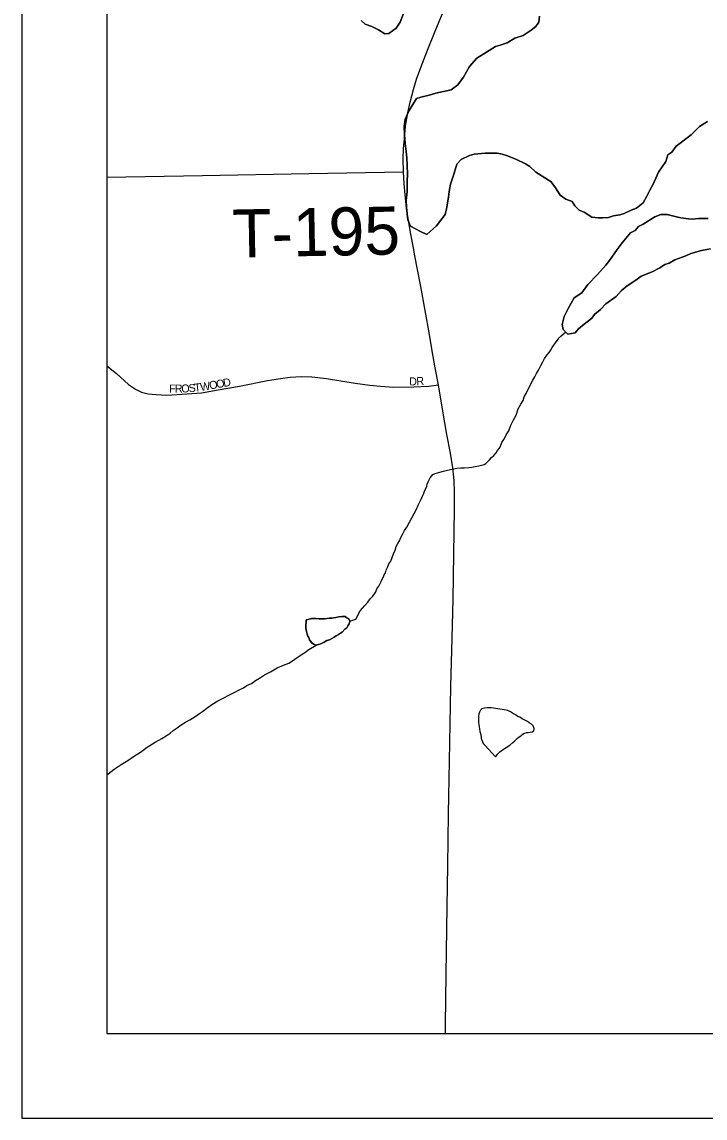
# Model space of a CAD drawing. Extents: x 0 to 34, y 0 to 22.
# Drawn here: x 2.262 to 3.071, y 14.238 to 15.535 of the extents above; entities that cross this region are included whole.
import ezdxf

# ---------------------------------------------------------------- set-up
doc = ezdxf.new("R2010")
doc.units = 0
for name, color, linetype in [('GM_X_County', 7, 'Continuous'), ('GM_X_Major_Lake', 7, 'Continuous'), ('GM_X_Major_River', 7, 'Continuous'), ('GM_X_Minor_Lake', 7, 'Continuous'), ('GM_X_Minor_River', 7, 'Continuous'), ('GM_X_State_Route', 7, 'Continuous'), ('GM_X_Township', 7, 'Continuous'), ('GM_X_Township_Road', 7, 'Continuous'), ('GM_X_Township_Road_Text', 7, 'Continuous'), ('GM_X_Township_Subdivision', 7, 'Continuous'), ('GM_X_Township_Subdivision_Text', 7, 'Continuous'), ('SH_Data', 7, 'Continuous')]:
    doc.layers.add(name, color=color, linetype=linetype)

msp = doc.modelspace()

# ---------------------------------------------------------------- linework, layer by layer
at = {"layer": 'GM_X_County'}
msp.add_lwpolyline([(9.1622, 14.342), (9.1622, 21.1385), (2.3622, 21.1385), (2.3622, 14.3385), (9.0003, 14.3385)], dxfattribs=at)
at = {"layer": 'GM_X_Major_Lake'}
for points in [[(2.6632, 15.5365), (2.6681, 15.5324), (2.6761, 15.5295), (2.6837, 15.5254), (2.6914, 15.5209), (2.6963, 15.5214), (2.7049, 15.5276), (2.7094, 15.5345), (2.7134, 15.5448)], [(2.8745, 15.5419), (2.8738, 15.5347), (2.8701, 15.5293), (2.8648, 15.525), (2.8551, 15.5188), (2.8452, 15.5157), (2.8362, 15.5102), (2.8279, 15.5075), (2.8226, 15.5059), (2.8117, 15.4993), (2.8004, 15.4919), (2.7918, 15.4823), (2.7844, 15.4697), (2.7777, 15.4605), (2.7698, 15.4547), (2.7517, 15.4506), (2.7438, 15.4483), (2.7339, 15.4459), (2.729, 15.4443), (2.7201, 15.4301), (2.7153, 15.4198), (2.7143, 15.4114), (2.7148, 15.4015), (2.7156, 15.3909), (2.7165, 15.3818), (2.7173, 15.3742), (2.7178, 15.3655), (2.7183, 15.3544), (2.718, 15.3468), (2.7178, 15.3343), (2.7168, 15.3236), (2.7169, 15.3153), (2.7186, 15.3009), (2.7217, 15.2933), (2.7335, 15.287), (2.7411, 15.2833), (2.7524, 15.2937), (2.7628, 15.3071), (2.7643, 15.314), (2.7664, 15.3254), (2.7678, 15.3368), (2.7692, 15.3429), (2.7733, 15.3559), (2.7765, 15.3666), (2.7818, 15.372), (2.7916, 15.3767), (2.7972, 15.3786), (2.8101, 15.3796), (2.8245, 15.3797), (2.8302, 15.3783), (2.8355, 15.3768), (2.8466, 15.3724), (2.858, 15.3672), (2.8629, 15.3639), (2.8702, 15.3571), (2.8885, 15.3456), (2.8936, 15.3388), (2.899, 15.3298), (2.9058, 15.3253), (2.9131, 15.3223), (2.9162, 15.3174), (2.9215, 15.3122), (2.9272, 15.31), (2.9364, 15.304), (2.944, 15.303), (2.9493, 15.303)], [(2.9493, 15.303), (2.9561, 15.3035), (2.9621, 15.3055), (2.9697, 15.3067), (2.9746, 15.3083), (2.9829, 15.3122), (2.9893, 15.3146), (2.9972, 15.3211), (3.0016, 15.3288), (3.005, 15.3357), (3.0091, 15.3429), (3.0153, 15.3571), (3.0239, 15.3697), (3.0264, 15.3778), (3.0313, 15.3809), (3.0362, 15.3878), (3.0542, 15.4013), (3.0639, 15.4113), (3.0733, 15.4171)], [(3.0743, 15.3024), (3.0629, 15.3022), (3.0558, 15.3017), (3.0508, 15.3021), (3.0417, 15.3031), (3.0368, 15.3042), (3.0258, 15.3071), (3.0182, 15.3073), (3.011, 15.3042), (2.9971, 15.2957), (2.9915, 15.2929), (2.9877, 15.288), (2.9821, 15.2856), (2.9724, 15.2737), (2.9664, 15.2656), (2.9575, 15.2526), (2.953, 15.2472), (2.9433, 15.2361), (2.9316, 15.2242), (2.9246, 15.2146), (2.9155, 15.2087), (2.9085, 15.1961), (2.9037, 15.1866), (2.9015, 15.177), (2.9027, 15.171), (2.9081, 15.1657), (2.9168, 15.167), (2.9205, 15.1719), (2.9273, 15.1774), (2.9359, 15.1839), (2.94, 15.1893), (2.9468, 15.1947), (2.9531, 15.2016), (2.9652, 15.2101), (2.9715, 15.2171), (2.9783, 15.2228), (2.9884, 15.2294), (2.9948, 15.2341), (3.008, 15.2392), (3.017, 15.2439), (3.0227, 15.2481), (3.028, 15.2497), (3.0347, 15.2536), (3.0479, 15.2583), (3.0536, 15.261), (3.0664, 15.2646), (3.077, 15.2663)]]:
    msp.add_lwpolyline(points, dxfattribs=at)
at = {"layer": 'GM_X_Major_River'}
for points in [[(2.7134, 15.5448), (2.7094, 15.5345), (2.7049, 15.5276), (2.6963, 15.5214), (2.6914, 15.5209), (2.6837, 15.5254), (2.6761, 15.5295), (2.6681, 15.5324), (2.6632, 15.5365)], [(2.9493, 15.303), (2.944, 15.303), (2.9364, 15.304), (2.9272, 15.31), (2.9215, 15.3122), (2.9162, 15.3174), (2.9131, 15.3223), (2.9058, 15.3253), (2.899, 15.3298), (2.8936, 15.3388), (2.8885, 15.3456), (2.8702, 15.3571), (2.8629, 15.3639), (2.858, 15.3672), (2.8466, 15.3724), (2.8355, 15.3768), (2.8302, 15.3783), (2.8245, 15.3797), (2.8101, 15.3796), (2.7972, 15.3786), (2.7916, 15.3767), (2.7818, 15.372), (2.7765, 15.3666), (2.7733, 15.3559), (2.7692, 15.3429), (2.7678, 15.3368), (2.7664, 15.3254), (2.7643, 15.314), (2.7628, 15.3071), (2.7524, 15.2937), (2.7411, 15.2833), (2.7335, 15.287), (2.7217, 15.2933), (2.7186, 15.3009), (2.7169, 15.3153), (2.7168, 15.3236), (2.7178, 15.3343), (2.718, 15.3468), (2.7183, 15.3544), (2.7178, 15.3655), (2.7173, 15.3742), (2.7165, 15.3818), (2.7156, 15.3909), (2.7148, 15.4015), (2.7143, 15.4114), (2.7153, 15.4198), (2.7201, 15.4301), (2.729, 15.4443), (2.7339, 15.4459), (2.7438, 15.4483), (2.7517, 15.4506), (2.7698, 15.4547), (2.7777, 15.4605), (2.7844, 15.4697), (2.7918, 15.4823), (2.8004, 15.4919), (2.8117, 15.4993), (2.8226, 15.5059), (2.8279, 15.5075), (2.8362, 15.5102), (2.8452, 15.5157), (2.8551, 15.5188), (2.8648, 15.525), (2.8701, 15.5293), (2.8738, 15.5347), (2.8745, 15.5419)], [(3.0733, 15.4171), (3.0639, 15.4113), (3.0542, 15.4013), (3.0362, 15.3878), (3.0313, 15.3809), (3.0264, 15.3778), (3.0239, 15.3697), (3.0153, 15.3571), (3.0091, 15.3429), (3.005, 15.3357), (3.0016, 15.3288), (2.9972, 15.3211), (2.9893, 15.3146), (2.9829, 15.3122), (2.9746, 15.3083), (2.9697, 15.3067), (2.9621, 15.3055), (2.9561, 15.3035), (2.9493, 15.303)], [(3.077, 15.2663), (3.0664, 15.2646), (3.0536, 15.261), (3.0479, 15.2583), (3.0347, 15.2536), (3.028, 15.2497), (3.0227, 15.2481), (3.017, 15.2439), (3.008, 15.2392), (2.9948, 15.2341), (2.9884, 15.2294), (2.9783, 15.2228), (2.9715, 15.2171), (2.9652, 15.2101), (2.9531, 15.2016), (2.9468, 15.1947), (2.94, 15.1893), (2.9359, 15.1839), (2.9273, 15.1774), (2.9205, 15.1719), (2.9168, 15.167), (2.9081, 15.1657), (2.9027, 15.171), (2.9015, 15.177), (2.9037, 15.1866), (2.9085, 15.1961), (2.9155, 15.2087), (2.9246, 15.2146), (2.9316, 15.2242), (2.9433, 15.2361), (2.953, 15.2472), (2.9575, 15.2526), (2.9664, 15.2656), (2.9724, 15.2737), (2.9821, 15.2856), (2.9877, 15.288), (2.9915, 15.2929), (2.9971, 15.2957), (3.011, 15.3042), (3.0182, 15.3073), (3.0258, 15.3071), (3.0368, 15.3042), (3.0417, 15.3031), (3.0508, 15.3021), (3.0558, 15.3017), (3.0629, 15.3022), (3.0743, 15.3024)]]:
    msp.add_lwpolyline(points, dxfattribs=at)
at = {"layer": 'GM_X_Minor_Lake'}
for points in [[(2.5984, 14.8276), (2.5992, 14.8278), (2.6019, 14.8286), (2.6049, 14.8291), (2.6099, 14.8292), (2.6137, 14.8289), (2.6171, 14.829), (2.6198, 14.829), (2.6232, 14.8291), (2.6258, 14.8296), (2.6285, 14.8296), (2.6308, 14.8301), (2.6334, 14.8305), (2.6368, 14.831), (2.6403, 14.8314), (2.6425, 14.8315), (2.6444, 14.8315), (2.6464, 14.83), (2.6487, 14.8289), (2.6499, 14.8259), (2.6492, 14.8229), (2.6477, 14.8206), (2.6463, 14.8182), (2.644, 14.8167), (2.6407, 14.8132), (2.6388, 14.812), (2.6366, 14.8104), (2.6339, 14.8088), (2.6313, 14.8072), (2.6287, 14.8057), (2.6257, 14.8041), (2.6226, 14.8032), (2.6196, 14.8013), (2.6178, 14.8005), (2.6155, 14.7993), (2.6129, 14.7984), (2.6102, 14.7976), (2.6068, 14.7987), (2.6048, 14.8005), (2.6021, 14.8039), (2.6013, 14.8066), (2.6001, 14.8084), (2.5993, 14.8107), (2.5988, 14.8137), (2.5984, 14.816), (2.5979, 14.8187), (2.5984, 14.8276)], [(2.5984, 14.8276), (2.5979, 14.8187), (2.5984, 14.816), (2.5988, 14.8137), (2.5993, 14.8107), (2.6001, 14.8084), (2.6013, 14.8066), (2.6021, 14.8039), (2.6048, 14.8005), (2.6068, 14.7987), (2.6102, 14.7976), (2.6129, 14.7984), (2.6155, 14.7993), (2.6178, 14.8005), (2.6196, 14.8013), (2.6226, 14.8032), (2.6257, 14.8041), (2.6287, 14.8057), (2.6313, 14.8072), (2.6339, 14.8088), (2.6366, 14.8104), (2.6388, 14.812), (2.6407, 14.8132), (2.644, 14.8167)], [(2.644, 14.8167), (2.6463, 14.8182), (2.6477, 14.8206), (2.6492, 14.8229), (2.6499, 14.8259), (2.6487, 14.8289), (2.6464, 14.83), (2.6444, 14.8315), (2.6425, 14.8315), (2.6403, 14.8314), (2.6368, 14.831), (2.6334, 14.8305), (2.6308, 14.8301), (2.6285, 14.8296), (2.6258, 14.8296), (2.6232, 14.8291), (2.6198, 14.829), (2.6171, 14.829), (2.6137, 14.8289), (2.6099, 14.8292), (2.6049, 14.8291), (2.6019, 14.8286), (2.5992, 14.8278), (2.5984, 14.8276)], [(2.8328, 14.7212), (2.82, 14.7233), (2.8174, 14.7236), (2.8151, 14.7235), (2.8124, 14.7235), (2.809, 14.723), (2.8064, 14.7222), (2.8045, 14.7206), (2.8034, 14.7183), (2.8027, 14.7164), (2.8024, 14.7133), (2.8021, 14.7114), (2.8021, 14.708), (2.8022, 14.7061), (2.8026, 14.7038), (2.803, 14.7012), (2.8035, 14.6985), (2.8039, 14.6955), (2.8052, 14.6921), (2.8056, 14.6875), (2.8061, 14.6853), (2.8077, 14.6815), (2.81, 14.6789), (2.8225, 14.6655)], [(2.8225, 14.6655), (2.8233, 14.6662), (2.8247, 14.6686), (2.8277, 14.6713), (2.8307, 14.674), (2.8393, 14.6795), (2.843, 14.6827), (2.8449, 14.6842), (2.8468, 14.6862), (2.8486, 14.6878), (2.8505, 14.6893), (2.8524, 14.6905), (2.8554, 14.6932), (2.8572, 14.6937), (2.8591, 14.6945), (2.861, 14.6945), (2.8633, 14.6949), (2.866, 14.695), (2.8678, 14.6962), (2.8682, 14.6992), (2.8669, 14.7022), (2.865, 14.7041), (2.8623, 14.7059), (2.8604, 14.7074), (2.8581, 14.7085), (2.8557, 14.7096), (2.8538, 14.7107), (2.8511, 14.7125), (2.8488, 14.7133), (2.8461, 14.7151), (2.8426, 14.7173), (2.8403, 14.7188), (2.8369, 14.7202), (2.8349, 14.7209), (2.8328, 14.7212)]]:
    msp.add_lwpolyline(points, dxfattribs=at)
at = {"layer": 'GM_X_Minor_River'}
for points in [[(2.6821, 14.8643), (2.6843, 14.8674), (2.6854, 14.8697), (2.6869, 14.8728), (2.6883, 14.8759), (2.6898, 14.8786), (2.6905, 14.8809), (2.692, 14.8832), (2.693, 14.8863), (2.6945, 14.8897), (2.6963, 14.894), (2.6985, 14.897), (2.6999, 14.9013), (2.7017, 14.9059), (2.7035, 14.9101), (2.7049, 14.9143), (2.7068, 14.9178), (2.7086, 14.9212), (2.7104, 14.9251), (2.7126, 14.9293), (2.7148, 14.9332), (2.7174, 14.9374), (2.7206, 14.9432), (2.7232, 14.9482), (2.7261, 14.9536), (2.7287, 14.9586), (2.7308, 14.9632), (2.7327, 14.9671), (2.7345, 14.9705), (2.7359, 14.974), (2.737, 14.9763), (2.7381, 14.9786), (2.741, 14.9859), (2.7417, 14.9882), (2.7428, 14.9909), (2.7439, 14.9932), (2.7449, 14.9955), (2.7483, 14.9994), (2.7509, 15.0006), (2.7536, 15.0014), (2.7566, 15.0022), (2.7607, 15.0035), (2.7657, 15.0047), (2.7713, 15.006), (2.7766, 15.0069), (2.7812, 15.0074), (2.7854, 15.0075), (2.7907, 15.008), (2.7945, 15.0084), (2.7983, 15.0089), (2.8025, 15.0098), (2.8059, 15.0106), (2.8089, 15.0114), (2.8108, 15.0126), (2.8126, 15.0142), (2.8152, 15.0169), (2.8178, 15.0196), (2.8204, 15.022), (2.823, 15.0251), (2.8249, 15.0278), (2.8267, 15.0305), (2.8282, 15.0332), (2.83, 15.0374), (2.8329, 15.042), (2.8351, 15.0466), (2.838, 15.0513), (2.8405, 15.0578), (2.8438, 15.0643), (2.8467, 15.0697), (2.8492, 15.0774), (2.8525, 15.0828), (2.8551, 15.0871), (2.8565, 15.0913), (2.8587, 15.0955), (2.8642, 15.1067), (2.8667, 15.1113), (2.8689, 15.1151), (2.8711, 15.119), (2.8733, 15.1229), (2.8762, 15.1286), (2.8784, 15.1329), (2.8806, 15.1367), (2.8832, 15.1406), (2.8858, 15.1437), (2.8876, 15.1464), (2.8894, 15.1499), (2.8916, 15.1526), (2.8935, 15.1553), (2.8953, 15.158), (2.8979, 15.1611), (2.8998, 15.163), (2.9056, 15.1682)], [(2.6499, 14.8259), (2.6571, 14.8284), (2.6622, 14.8384), (2.6677, 14.8446), (2.6711, 14.8485), (2.674, 14.8523), (2.677, 14.8558), (2.6792, 14.8582), (2.6807, 14.8609), (2.6821, 14.8643)], [(2.3622, 14.6444), (2.3637, 14.6455), (2.3708, 14.651), (2.3791, 14.6565), (2.3873, 14.6613), (2.3937, 14.666), (2.4023, 14.6711), (2.4102, 14.677), (2.4195, 14.6829), (2.4274, 14.6873), (2.4327, 14.6905), (2.4372, 14.6936), (2.4409, 14.6968), (2.4454, 14.6999), (2.4503, 14.7034), (2.4555, 14.7066), (2.4604, 14.7094), (2.4668, 14.7133), (2.4709, 14.7161), (2.4754, 14.7192), (2.4806, 14.7231), (2.4866, 14.7275), (2.4938, 14.7318), (2.5009, 14.7354), (2.5069, 14.7386), (2.5129, 14.7418), (2.519, 14.7449), (2.5239, 14.747), (2.528, 14.7501), (2.5336, 14.7525), (2.5381, 14.7557), (2.543, 14.7588), (2.549, 14.7624), (2.5561, 14.7663), (2.564, 14.7707), (2.5716, 14.7739), (2.5776, 14.7763), (2.581, 14.7783), (2.5888, 14.7838), (2.5922, 14.7862), (2.5967, 14.7889), (2.6016, 14.7925), (2.6102, 14.7976)]]:
    msp.add_lwpolyline(points, dxfattribs=at)
at = {"layer": 'GM_X_State_Route'}
for points in [[(2.7267, 15.2601), (2.7256, 15.2656), (2.7219, 15.286), (2.7172, 15.3146), (2.7154, 15.3303), (2.7142, 15.3438), (2.7134, 15.3572), (2.7132, 15.3729), (2.7136, 15.3848), (2.7145, 15.3972), (2.716, 15.4116), (2.7188, 15.4273), (2.7214, 15.4401), (2.7254, 15.4548), (2.7289, 15.467), (2.7339, 15.481), (2.7418, 15.5016), (2.7508, 15.5239), (2.7703, 15.571)], [(2.7633, 14.3385), (2.7634, 14.3488), (2.7641, 14.4083), (2.7652, 14.4887), (2.7658, 14.5366), (2.7669, 14.5982), (2.768, 14.6605), (2.7697, 14.7488), (2.7712, 14.8061), (2.7722, 14.852), (2.774, 14.9584), (2.774, 14.9784), (2.7735, 14.9923), (2.7717, 15.0074), (2.769, 15.0246), (2.7649, 15.0467), (2.7602, 15.0744), (2.7548, 15.1057), (2.7508, 15.1259), (2.7473, 15.1459), (2.7441, 15.165), (2.7339, 15.2218), (2.7267, 15.2601)]]:
    msp.add_lwpolyline(points, dxfattribs=at)
at = {"layer": 'GM_X_Township'}
msp.add_lwpolyline([(2.3622, 19.6335), (2.3622, 14.3385), (4.4492, 14.3385)], dxfattribs=at)
at = {"layer": 'GM_X_Township_Road'}
msp.add_lwpolyline([(2.7134, 15.3572), (2.6016, 15.3552), (2.4757, 15.353), (2.3622, 15.3508)], dxfattribs=at)
at = {"layer": 'GM_X_Township_Subdivision'}
msp.add_lwpolyline([(2.3622, 15.1281), (2.3736, 15.1189), (2.388, 15.106), (2.3962, 15.1003), (2.4032, 15.097), (2.4114, 15.095), (2.4206, 15.094), (2.4333, 15.0935), (2.4572, 15.0948), (2.4742, 15.0963), (2.4941, 15.0998), (2.5195, 15.1042), (2.5523, 15.1107), (2.568, 15.1132), (2.5792, 15.1147), (2.5929, 15.1154), (2.6049, 15.1149), (2.6223, 15.1132), (2.6564, 15.1077), (2.6736, 15.1052), (2.6863, 15.104), (2.702, 15.1027), (2.7256, 15.1032), (2.7433, 15.1042), (2.7548, 15.1057)], dxfattribs=at)
at = {"layer": 'SH_Data'}
for p, q in [((2.2617, 21.2383), (2.2617, 14.2383)), ((2.2617, 14.2383), (9.2617, 14.2383))]:
    msp.add_line(p, q, dxfattribs=at)

# ---------------------------------------------------------------- texts
at = {"layer": 'GM_X_Township_Road_Text'}
msp.add_text('T-195', height=0.05682, rotation=1.1227, dxfattribs=at).set_placement((2.5114, 15.2561))
at = {"layer": 'GM_X_Township_Subdivision_Text'}
for s, rotation, p in [('F', 0.082, (2.4361, 15.0965)), ('R', 0.0729, (2.4428, 15.0965)), ('O', 1.6603, (2.4506, 15.0965)), ('S', 5.0571, (2.4595, 15.0968)), ('T', 6.1461, (2.4663, 15.0974)), ('W', 9.4143, (2.4736, 15.0982)), ('O', 10.3038, (2.4844, 15.1)), ('O', 10.3068, (2.4926, 15.1015)), ('D', 10.2853, (2.5008, 15.103)), ('D', 1.8363, (2.7204, 15.1048)), ('R', 3.6098, (2.729, 15.1051))]:
    msp.add_text(s, height=0.00947, rotation=rotation, dxfattribs=at).set_placement(p)

doc.saveas('drawing.dxf')
